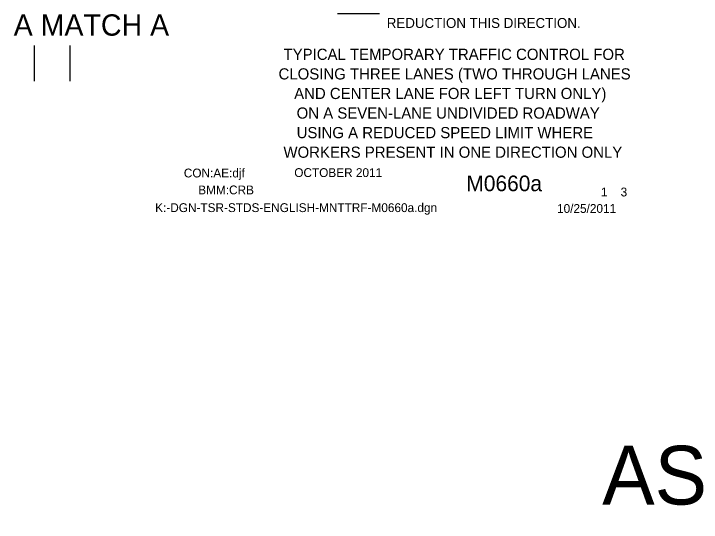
# Model space of a CAD drawing. Extents: x 16544 to 19504, y 5662 to 6922.
# Drawn here: x 16971.2 to 17454.2, y 5715.7 to 6073.1 of the extents above; entities that cross this region are included whole.
import ezdxf

# ---------------------------------------------------------------- set-up
doc = ezdxf.new("R2010")
doc.units = 0
for name, color, linetype in [('BORDER', 7, 'Continuous'), ('BORDER_SIGNAL_WO', 7, 'Continuous'), ('PAVT_EDGE_EX', 7, 'Continuous'), ('TYPICAL_TEXT_DIMEN_PR', 7, 'Continuous')]:
    doc.layers.add(name, color=color, linetype=linetype)

msp = doc.modelspace()

# ---------------------------------------------------------------- linework, layer by layer
at = {"layer": 'PAVT_EDGE_EX'}
for points in [[(16985.78, 6025.74), (16985.78, 6050.74)], [(16985.78, 6025.74), (16985.78, 6050.74)], [(17010.78, 6025.74), (17010.78, 6050.74)], [(17010.78, 6025.74), (17010.78, 6050.74)]]:
    msp.add_lwpolyline(points, dxfattribs=at)
at = {"layer": 'TYPICAL_TEXT_DIMEN_PR'}
msp.add_line((17228.1, 6073.12), (17198.66, 6073.12), dxfattribs=at)

# ---------------------------------------------------------------- texts
at = {"layer": 'BORDER'}
for s, p in [('TYPICAL TEMPORARY TRAFFIC CONTROL FOR', (17160.75, 6040.69)), ('CLOSING THREE LANES (TWO THROUGH LANES', (17157.25, 6026.92)), ('AND CENTER LANE FOR LEFT TURN ONLY)', (17168.2, 6013.16)), ('ON A SEVEN-LANE UNDIVIDED ROADWAY ', (17169.95, 5999.4)), ('USING A REDUCED SPEED LIMIT WHERE ', (17169.95, 5985.63)), ('WORKERS PRESENT IN ONE DIRECTION ONLY', (17160.69, 5971.87))]:
    msp.add_text(s, height=7.8528, dxfattribs=at).set_placement(p)
at = {"layer": 'BORDER_SIGNAL_WO'}
for s, height, p in [('CON:AE:djf', 6.2, (17090.69, 5958.06)), ('    OCTOBER 2011    ', 6.2, (17159.08, 5958.34)), ('    M0660a   ', 11, (17272.86, 5948.38)), ('BMM:CRB   ', 6.2, (17100.81, 5946.17)), (' 1    3 ', 6.2, (17381.45, 5944.7)), ('K:-DGN-TSR-STDS-ENGLISH-MNTTRF-M0660a.dgn        ', 6.2, (17070.55, 5933.71)), ('10/25/2011    ', 6.2, (17352.93, 5933.13)), ('AS = 0.8 for Sign Cells', 41.2877, (17384.66, 5728.12))]:
    msp.add_text(s, height=height, dxfattribs=at).set_placement(p)
at = {"layer": 'TYPICAL_TEXT_DIMEN_PR'}
for s, height, p in [('A MATCH A', 15, (16971.15, 6057.7)), ('REDUCTION THIS DIRECTION.', 7, (17233.28, 6063.13))]:
    msp.add_text(s, height=height, dxfattribs=at).set_placement(p)

doc.saveas('drawing.dxf')
